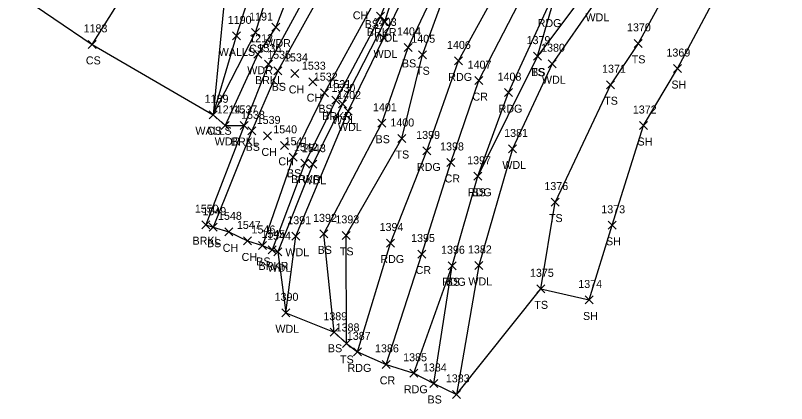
# Model space of a CAD drawing. Extents: x 1441651 to 1442140, y 243798 to 245625.
# Drawn here: x 1441936.1 to 1442128.7, y 245257.1 to 245354.1 of the extents above; entities that cross this region are included whole.
import ezdxf

# ---------------------------------------------------------------- set-up
doc = ezdxf.new("R2010")
doc.units = 0
for name, color, linetype in [('L_A', 7, 'Continuous'), ('L_I', 7, 'Continuous'), ('L_TIC', 7, 'Continuous'), ('LAWA', 7, 'Continuous'), ('LAWE', 7, 'Continuous'), ('LELB', 7, 'Continuous'), ('LSOGP', 7, 'Continuous'), ('LWS', 7, 'Continuous'), ('P_A', 7, 'Continuous'), ('P_I', 7, 'Continuous'), ('P_TIC', 7, 'Continuous'), ('PEU', 7, 'Continuous'), ('PRC', 7, 'Continuous')]:
    doc.layers.add(name, color=color, linetype=linetype)

msp = doc.modelspace()

# ---------------------------------------------------------------- linework, layer by layer
at = {"layer": 'L_TIC'}
for points in [[(1442026.29, 245352.92), (1442028.29, 245354.92)], [(1442028.29, 245352.92), (1442026.29, 245354.92)], [(1442000.16, 245350.18), (1442002.16, 245352.18)], [(1442002.16, 245350.18), (1442000.16, 245352.18)], [(1442027.33, 245351.53), (1442029.33, 245353.53)], [(1442029.33, 245351.53), (1442027.33, 245353.53)], [(1441990.35, 245347.99), (1441992.35, 245349.99)], [(1441992.35, 245347.99), (1441990.35, 245349.99)], [(1441995.05, 245348.81), (1441997.05, 245350.81)], [(1441997.05, 245348.81), (1441995.05, 245350.81)], [(1442027.14, 245347.48), (1442029.14, 245349.48)], [(1442029.14, 245347.48), (1442027.14, 245349.48)], [(1442090.63, 245346.12), (1442092.63, 245348.12)], [(1442092.63, 245346.12), (1442090.63, 245348.12)], [(1441954.27, 245345.86), (1441956.27, 245347.86)], [(1441956.27, 245345.86), (1441954.27, 245347.86)], [(1442033.2, 245345.11), (1442035.2, 245347.11)], [(1442035.2, 245345.11), (1442033.2, 245347.11)], [(1441995.64, 245343.41), (1441997.64, 245345.41)], [(1441997.64, 245343.41), (1441995.64, 245345.41)], [(1442036.76, 245343.27), (1442038.76, 245345.27)], [(1442038.76, 245343.27), (1442036.76, 245345.27)], [(1442065.47, 245342.93), (1442067.47, 245344.93)], [(1442067.47, 245342.93), (1442065.47, 245344.93)], [(1442065.47, 245342.93), (1442067.47, 245344.93)], [(1442067.47, 245342.93), (1442065.47, 245344.93)], [(1441998.31, 245340.93), (1442000.31, 245342.93)], [(1442000.31, 245340.93), (1441998.31, 245342.93)], [(1442069.18, 245341.03), (1442071.18, 245343.03)], [(1442071.18, 245341.03), (1442069.18, 245343.03)], [(1442000.68, 245339.27), (1442002.68, 245341.27)], [(1442002.68, 245339.27), (1442000.68, 245341.27)], [(1442004.9, 245338.6), (1442006.9, 245340.6)], [(1442006.9, 245338.6), (1442004.9, 245340.6)], [(1442100.45, 245339.82), (1442102.45, 245341.82)], [(1442102.45, 245339.82), (1442100.45, 245341.82)], [(1442009.36, 245336.54), (1442011.36, 245338.54)], [(1442011.36, 245336.54), (1442009.36, 245338.54)], [(1442083.74, 245335.78), (1442085.74, 245337.78)], [(1442085.74, 245335.78), (1442083.74, 245337.78)], [(1442012.33, 245333.79), (1442014.33, 245335.79)], [(1442014.33, 245333.79), (1442012.33, 245335.79)], [(1442015.14, 245331.93), (1442017.14, 245333.93)], [(1442017.14, 245331.93), (1442015.14, 245333.93)], [(1442016.83, 245330.97), (1442018.83, 245332.97)], [(1442018.83, 245330.97), (1442016.83, 245332.97)], [(1442018.24, 245329.2), (1442020.24, 245331.2)], [(1442020.24, 245329.2), (1442018.24, 245331.2)], [(1441984.51, 245328.27), (1441986.51, 245330.27)], [(1441986.51, 245328.27), (1441984.51, 245330.27)], [(1441984.51, 245328.27), (1441986.51, 245330.27)], [(1441986.51, 245328.27), (1441984.51, 245330.27)], [(1441987.52, 245325.61), (1441989.52, 245327.61)], [(1441989.52, 245325.61), (1441987.52, 245327.61)], [(1441992.28, 245325.59), (1441994.28, 245327.59)], [(1441994.28, 245325.59), (1441992.28, 245327.59)], [(1442026.62, 245326.16), (1442028.62, 245328.16)], [(1442028.62, 245326.16), (1442026.62, 245328.16)], [(1442092, 245325.58), (1442094, 245327.58)], [(1442094, 245325.58), (1442092, 245327.58)], [(1441994.17, 245324.26), (1441996.17, 245326.26)], [(1441996.17, 245324.26), (1441994.17, 245326.26)], [(1441998.07, 245322.98), (1442000.07, 245324.98)], [(1442000.07, 245322.98), (1441998.07, 245324.98)], [(1442031.62, 245322.34), (1442033.62, 245324.34)], [(1442033.62, 245322.34), (1442031.62, 245324.34)], [(1442002.29, 245320.63), (1442004.29, 245322.63)], [(1442004.29, 245320.63), (1442002.29, 245322.63)], [(1442059.29, 245319.73), (1442061.29, 245321.73)], [(1442061.29, 245319.73), (1442059.29, 245321.73)], [(1442004.48, 245317.66), (1442006.48, 245319.66)], [(1442006.48, 245317.66), (1442004.48, 245319.66)], [(1442007.36, 245316.18), (1442009.36, 245318.18)], [(1442009.36, 245316.18), (1442007.36, 245318.18)], [(1442009.38, 245315.92), (1442011.38, 245317.92)], [(1442011.38, 245315.92), (1442009.38, 245317.92)], [(1442050.62, 245312.9), (1442052.62, 245314.9)], [(1442052.62, 245312.9), (1442050.62, 245314.9)], [(1442069.95, 245306.45), (1442071.95, 245308.45)], [(1442071.95, 245306.45), (1442069.95, 245308.45)], [(1442069.95, 245306.45), (1442071.95, 245308.45)], [(1442071.95, 245306.45), (1442069.95, 245308.45)], [(1441982.7, 245300.8), (1441984.7, 245302.8)], [(1441984.7, 245300.8), (1441982.7, 245302.8)], [(1441984.52, 245300.17), (1441986.52, 245302.17)], [(1441986.52, 245300.17), (1441984.52, 245302.17)], [(1442084.12, 245300.65), (1442086.12, 245302.65)], [(1442086.12, 245300.65), (1442084.12, 245302.65)], [(1441988.4, 245299.01), (1441990.4, 245301.01)], [(1441990.4, 245299.01), (1441988.4, 245301.01)], [(1442005.13, 245297.92), (1442007.13, 245299.92)], [(1442007.13, 245297.92), (1442005.13, 245299.92)], [(1442012.15, 245298.51), (1442014.15, 245300.51)], [(1442014.15, 245298.51), (1442012.15, 245300.51)], [(1442017.73, 245298.13), (1442019.73, 245300.13)], [(1442019.73, 245298.13), (1442017.73, 245300.13)], [(1441993.11, 245296.74), (1441995.11, 245298.74)], [(1441995.11, 245296.74), (1441993.11, 245298.74)], [(1441996.83, 245295.61), (1441998.83, 245297.61)], [(1441998.83, 245295.61), (1441996.83, 245297.61)], [(1441999.26, 245294.5), (1442001.26, 245296.5)], [(1442001.26, 245294.5), (1441999.26, 245296.5)], [(1442000.66, 245294.02), (1442002.66, 245296.02)], [(1442002.66, 245294.02), (1442000.66, 245296.02)], [(1442044.15, 245290.53), (1442046.15, 245292.53)], [(1442046.15, 245290.53), (1442044.15, 245292.53)], [(1442050.82, 245290.62), (1442052.82, 245292.62)], [(1442052.82, 245290.62), (1442050.82, 245292.62)], [(1442066.31, 245284.77), (1442068.31, 245286.77)], [(1442068.31, 245284.77), (1442066.31, 245286.77)], [(1442078.37, 245281.99), (1442080.37, 245283.99)], [(1442080.37, 245281.99), (1442078.37, 245283.99)], [(1442002.62, 245278.78), (1442004.62, 245280.78)], [(1442004.62, 245278.78), (1442002.62, 245280.78)], [(1442014.72, 245273.92), (1442016.72, 245275.92)], [(1442016.72, 245273.92), (1442014.72, 245275.92)], [(1442017.78, 245271.12), (1442019.78, 245273.12)], [(1442019.78, 245271.12), (1442017.78, 245273.12)], [(1442039.59, 245261.12), (1442041.59, 245263.12)], [(1442041.59, 245261.12), (1442039.59, 245263.12)], [(1442045.29, 245258.4), (1442047.29, 245260.4)], [(1442047.29, 245258.4), (1442045.29, 245260.4)]]:
    msp.add_lwpolyline(points, dxfattribs=at)
at = {"layer": 'LAWA'}
for points in [[(1441938.82, 245423.16), (1441966.59, 245419.59), (1441980.43, 245407.31), (1441994.99, 245393.97), (1442005.69, 245385.38), (1442010.09, 245391.87), (1442016.01, 245382.46), (1442013.07, 245379.25), (1442007.39, 245367.36), (1442001.16, 245351.18), (1441996.64, 245344.41), (1441988.52, 245326.61)], [(1442003.62, 245279.78), (1442006.13, 245298.92), (1442019.24, 245330.2), (1442028.14, 245348.48), (1442037.74, 245368.51), (1442033.75, 245369.5), (1442028.33, 245352.53), (1442017.83, 245331.97), (1442010.38, 245316.92), (1442001.66, 245295.02)], [(1442081.06, 245357.62), (1442070.18, 245342.03), (1442060.29, 245320.73), (1442051.82, 245291.62), (1442046.29, 245259.4)]]:
    msp.add_lwpolyline(points, dxfattribs=at)
at = {"layer": 'LAWE'}
for points in [[(1442099.33, 245492.7), (1442082.17, 245474.83), (1442073.96, 245459.56), (1442071.04, 245454.67), (1442067.5, 245447.08), (1442064.77, 245439.02), (1442060.82, 245433.99), (1442057.71, 245424.57), (1442056.02, 245422.42), (1442050.95, 245416.77), (1442046.42, 245406.15), (1442038.47, 245397.39), (1442033, 245390.02), (1442022.03, 245379.96), (1442015.44, 245373.01), (1442011.82, 245364.95), (1441999.31, 245341.93), (1441993.28, 245326.59), (1441983.7, 245301.8)], [(1442108.8, 245476.47), (1442096.83, 245461.7), (1442085.94, 245448.64), (1442079.45, 245435.79), (1442078.13, 245432.44), (1442074.22, 245419.93), (1442069.91, 245412.33), (1442066.17, 245406.44), (1442060.08, 245400.81), (1442053.87, 245394.97), (1442048.8, 245389.02), (1442033.75, 245369.5), (1442027.29, 245353.92), (1442016.14, 245332.93), (1442008.36, 245317.18), (1442000.26, 245295.5)]]:
    msp.add_lwpolyline(points, dxfattribs=at)
at = {"layer": 'LELB'}
for points in [[(1442102.46, 245487.56), (1442084.35, 245473.24), (1442077.16, 245458.74), (1442072.72, 245452.8), (1442069.73, 245445.65), (1442066.87, 245437.14), (1442063.41, 245431.6), (1442060.35, 245422.41), (1442058.71, 245418.73), (1442054.41, 245414.05), (1442047.26, 245402.98), (1442041.76, 245394.88), (1442035.1, 245387.22), (1442025.14, 245377.83), (1442014.24, 245362.92), (1442001.68, 245340.27), (1441995.17, 245325.26), (1441985.52, 245301.17)], [(1442107.48, 245478.04), (1442095.11, 245463.14), (1442085.12, 245450.23), (1442079.93, 245439.38), (1442074.02, 245430.6), (1442072.19, 245422.42), (1442067.6, 245415.77), (1442063.53, 245410.87), (1442058.94, 245403.45), (1442051.47, 245396.66), (1442047.36, 245390.55), (1442031.62, 245371.64), (1442024.89, 245355.94), (1442013.33, 245334.79), (1442005.48, 245318.66), (1441997.83, 245296.61)], [(1442128.7, 245453.17), (1442114.47, 245439.46), (1442106.29, 245436.04), (1442091.13, 245416.25), (1442087.36, 245410.97), (1442078.92, 245407.7), (1442072.37, 245401.79), (1442078.66, 245393.32), (1442088.17, 245379.01), (1442078.35, 245359.72), (1442066.47, 245343.93), (1442051.62, 245313.9)], [(1442126.3, 245425.7), (1442121.34, 245419.96), (1442113.11, 245400.1), (1442105.87, 245373.18), (1442091.63, 245347.12), (1442084.74, 245336.78), (1442070.95, 245307.45)], [(1442066.47, 245343.93), (1442078.11, 245383.77), (1442072.28, 245394.26)], [(1441955.27, 245346.86), (1441965.21, 245362.63), (1441976.13, 245373.64), (1441994.99, 245393.97), (1441992.5, 245375.66), (1441988.38, 245359.29), (1441985.51, 245329.27), (1441996.05, 245349.81), (1442001.58, 245367.37), (1442003.86, 245377.37), (1442005.69, 245385.38), (1442010.09, 245391.87)], [(1442018.78, 245272.12), (1442018.73, 245299.13), (1442032.62, 245323.34), (1442037.76, 245344.27), (1442043.41, 245359.74), (1442052.17, 245365.32), (1442056.49, 245374.23), (1442057.59, 245382.34)], [(1442015.72, 245274.92), (1442013.15, 245299.51), (1442027.62, 245327.16), (1442034.2, 245346.11), (1442043.81, 245366.33)], [(1442067.31, 245285.77), (1442070.95, 245307.45)], [(1442040.59, 245262.12), (1442045.15, 245291.53)]]:
    msp.add_lwpolyline(points, dxfattribs=at)
at = {"layer": 'LSOGP'}
msp.add_lwpolyline([(1441936.12, 245359.87), (1441955.27, 245346.86), (1441985.51, 245329.27), (1441988.52, 245326.61), (1441993.28, 245326.59), (1441983.7, 245301.8), (1441985.52, 245301.17), (1441989.4, 245300.01), (1441994.11, 245297.74), (1441997.83, 245296.61), (1442000.26, 245295.5), (1442001.66, 245295.02), (1442003.62, 245279.78), (1442015.72, 245274.92), (1442018.78, 245272.12), (1442021.57, 245270.01), (1442028.67, 245266.9), (1442035.64, 245264.67), (1442040.59, 245262.12), (1442046.29, 245259.4), (1442067.31, 245285.77), (1442079.37, 245282.99), (1442085.12, 245301.65), (1442093, 245326.58), (1442101.45, 245340.82), (1442116.12, 245368.4)], dxfattribs=at)
at = {"layer": 'LWS'}
msp.add_lwpolyline([(1441985.51, 245329.27), (1441991.35, 245348.99), (1441998.11, 245370.16), (1442003.86, 245377.37), (1442013.07, 245379.25)], dxfattribs=at)
at = {"layer": 'P_TIC'}
for points in [[(1442045.73, 245341.73), (1442047.73, 245343.73)], [(1442047.73, 245341.73), (1442045.73, 245343.73)], [(1442050.82, 245336.8), (1442052.82, 245338.8)], [(1442052.82, 245336.8), (1442050.82, 245338.8)], [(1442058.29, 245333.8), (1442060.29, 245335.8)], [(1442060.29, 245333.8), (1442058.29, 245335.8)], [(1442037.9, 245319.23), (1442039.9, 245321.23)], [(1442039.9, 245319.23), (1442037.9, 245321.23)], [(1442043.86, 245316.35), (1442045.86, 245318.35)], [(1442045.86, 245316.35), (1442043.86, 245318.35)], [(1442050.62, 245312.9), (1442052.62, 245314.9)], [(1442052.62, 245312.9), (1442050.62, 245314.9)], [(1442028.76, 245296.22), (1442030.76, 245298.22)], [(1442030.76, 245296.22), (1442028.76, 245298.22)], [(1442036.62, 245293.47), (1442038.62, 245295.47)], [(1442038.62, 245293.47), (1442036.62, 245295.47)], [(1442044.15, 245290.53), (1442046.15, 245292.53)], [(1442046.15, 245290.53), (1442044.15, 245292.53)], [(1442020.57, 245269.01), (1442022.57, 245271.01)], [(1442022.57, 245269.01), (1442020.57, 245271.01)], [(1442027.67, 245265.9), (1442029.67, 245267.9)], [(1442029.67, 245265.9), (1442027.67, 245267.9)], [(1442034.64, 245263.67), (1442036.64, 245265.67)], [(1442036.64, 245263.67), (1442034.64, 245265.67)]]:
    msp.add_lwpolyline(points, dxfattribs=at)
at = {"layer": 'PEU'}
for points in [[(1442021.57, 245270.01), (1442029.76, 245297.22), (1442038.9, 245320.23), (1442046.73, 245342.73), (1442056.78, 245360.96), (1442059.33, 245377.92), (1442059.51, 245384.26), (1442055.55, 245392.58), (1442060.31, 245397.75), (1442066.08, 245403.51)], [(1442035.64, 245264.67), (1442045.15, 245291.53), (1442051.62, 245313.9), (1442059.29, 245334.8), (1442069.06, 245356.18), (1442072.88, 245382.67), (1442066.08, 245403.51)]]:
    msp.add_lwpolyline(points, dxfattribs=at)
at = {"layer": 'PRC'}
msp.add_lwpolyline([(1442028.67, 245266.9), (1442037.62, 245294.47), (1442044.86, 245317.35), (1442051.82, 245337.8), (1442063.02, 245359.5), (1442065.73, 245381.39), (1442063.41, 245391.64), (1442060.31, 245397.75)], dxfattribs=at)

# ---------------------------------------------------------------- texts
at = {"layer": 'L_A'}
for s, p in [('CH', (1442020.38, 245353.12)), ('WDL', (1442078.48, 245352.62)), ('BS', (1442023.33, 245350.94)), ('BRKR', (1442023.89, 245348.92)), ('WDR', (1441998.52, 245346.18)), ('WDL', (1442025.75, 245347.53)), ('WALLS', (1441986.89, 245343.99)), ('CS', (1441994.49, 245344.81)), ('WDL', (1442025.56, 245343.48)), ('TS', (1442090.03, 245342.12)), ('CS', (1441953.71, 245341.86)), ('BS', (1442032.64, 245341.11)), ('WDR', (1441994, 245339.41)), ('TS', (1442036.17, 245339.27)), ('TS', (1442064.88, 245338.93)), ('BS', (1442064.91, 245338.93)), ('BRKL', (1441995.96, 245336.93)), ('WDL', (1442067.6, 245337.03)), ('BS', (1442000.12, 245335.27)), ('CH', (1442004.39, 245334.6)), ('SH', (1442099.94, 245335.82)), ('CH', (1442008.85, 245332.54)), ('TS', (1442083.15, 245331.78)), ('BS', (1442011.77, 245329.79)), ('BRKR', (1442012.73, 245327.93)), ('WDL', (1442015.25, 245326.97)), ('WDL', (1442016.66, 245325.2)), ('WALLS', (1441981.06, 245324.27)), ('CS', (1441983.96, 245324.27)), ('WDR', (1441985.88, 245321.61)), ('BRKL', (1441989.92, 245321.59)), ('BS', (1442026.06, 245322.16)), ('SH', (1442091.48, 245321.58)), ('BS', (1441993.61, 245320.26)), ('CH', (1441997.56, 245318.98)), ('TS', (1442031.03, 245318.34)), ('CH', (1442001.78, 245316.63)), ('WDL', (1442057.71, 245315.73)), ('BS', (1442003.92, 245313.66)), ('BRKR', (1442004.95, 245312.18)), ('WDL', (1442007.79, 245311.92)), ('BS', (1442050.06, 245308.9)), ('TS', (1442069.36, 245302.45)), ('TS', (1442069.36, 245302.45)), ('BRKL', (1441980.34, 245296.8)), ('BS', (1441983.96, 245296.17)), ('SH', (1442083.61, 245296.65)), ('CH', (1441987.89, 245295.01)), ('BS', (1442011.59, 245294.51)), ('TS', (1442017.14, 245294.13)), ('CH', (1441992.6, 245292.74)), ('WDL', (1442003.55, 245293.92)), ('BS', (1441996.27, 245291.61)), ('BRKR', (1441996.85, 245290.5)), ('WDL', (1441999.08, 245290.02)), ('BS', (1442043.6, 245286.53)), ('WDL', (1442049.24, 245286.62)), ('TS', (1442065.72, 245280.77)), ('SH', (1442077.86, 245277.99)), ('WDL', (1442001.04, 245274.78)), ('BS', (1442014.16, 245269.92)), ('TS', (1442017.19, 245267.12)), ('BS', (1442039.03, 245257.12))]:
    msp.add_text(s, height=2, dxfattribs=at).set_placement(p)
at = {"layer": 'L_I'}
for s, p in [('1190', (1441989.14, 245351.99)), ('1191', (1441994.49, 245352.81)), ('1183', (1441953.14, 245349.86)), ('1403', (1442025.37, 245351.48)), ('1370', (1442088.85, 245350.12)), ('1404', (1442031.42, 245349.11)), ('1213', (1441994.51, 245347.41)), ('1405', (1442034.99, 245347.27)), ('1379', (1442063.77, 245346.93)), ('1379', (1442063.77, 245346.93)), ('1536', (1441996.56, 245344.93)), ('1380', (1442067.4, 245345.03)), ('1535', (1441998.99, 245343.27)), ('1534', (1442003.2, 245342.6)), ('1369', (1442098.7, 245343.82)), ('1533', (1442007.66, 245340.54)), ('1371', (1442082.62, 245339.78)), ('1532', (1442010.64, 245337.79)), ('1531', (1442014.02, 245335.93)), ('1530', (1442015.05, 245334.97)), ('1402', (1442016.47, 245333.2)), ('1189', (1441983.38, 245332.27)), ('1189', (1441983.38, 245332.27)), ('1214', (1441986.39, 245329.61)), ('1537', (1441990.58, 245329.59)), ('1401', (1442025.41, 245330.16)), ('1372', (1442090.3, 245329.58)), ('1538', (1441992.47, 245328.26)), ('1539', (1441996.37, 245326.98)), ('1400', (1442029.76, 245326.34)), ('1540', (1442000.51, 245324.63)), ('1381', (1442058.17, 245323.73)), ('1541', (1442003.35, 245321.66)), ('1542', (1442005.67, 245320.18)), ('1543', (1442007.68, 245319.92)), ('1397', (1442048.93, 245316.9)), ('1376', (1442068.21, 245310.45)), ('1376', (1442068.21, 245310.45)), ('1550', (1441980.92, 245304.8)), ('1549', (1441982.82, 245304.17)), ('1373', (1442082.43, 245304.65)), ('1548', (1441986.71, 245303.01)), ('1391', (1442004.01, 245301.92)), ('1392', (1442010.45, 245302.51)), ('1393', (1442016.03, 245302.13)), ('1547', (1441991.42, 245300.74)), ('1546', (1441995.08, 245299.61)), ('1545', (1441997.57, 245298.5)), ('1544', (1441998.97, 245298.02)), ('1396', (1442042.41, 245294.53)), ('1382', (1442049.13, 245294.62)), ('1375', (1442064.61, 245288.77)), ('1374', (1442076.68, 245285.99)), ('1390', (1442000.84, 245282.78)), ('1389', (1442013.02, 245277.92)), ('1388', (1442016.09, 245275.12)), ('1384', (1442037.89, 245265.12)), ('1383', (1442043.6, 245262.4))]:
    msp.add_text(s, height=2, dxfattribs=at).set_placement(p)
at = {"layer": 'P_A'}
for s, p in [('RDG', (1442066.54, 245351.18)), ('RDG', (1442044.21, 245337.73)), ('CR', (1442050.25, 245332.8)), ('RDG', (1442056.78, 245329.8)), ('RDG', (1442036.39, 245315.23)), ('CR', (1442043.29, 245312.35)), ('RDG', (1442049.11, 245308.9)), ('RDG', (1442027.25, 245292.22)), ('CR', (1442036.06, 245289.47)), ('RDG', (1442042.64, 245286.53)), ('RDG', (1442019.06, 245265.01)), ('CR', (1442027.1, 245261.9)), ('RDG', (1442033.13, 245259.67))]:
    msp.add_text(s, height=2, dxfattribs=at).set_placement(p)
at = {"layer": 'P_I'}
for s, p in [('1406', (1442043.9, 245345.73)), ('1407', (1442049.05, 245340.8)), ('1408', (1442056.52, 245337.8)), ('1399', (1442036.2, 245323.23)), ('1398', (1442042.17, 245320.35)), ('1397', (1442048.93, 245316.9)), ('1394', (1442027.07, 245300.22)), ('1395', (1442034.93, 245297.47)), ('1396', (1442042.41, 245294.53)), ('1387', (1442018.88, 245273.01)), ('1386', (1442025.92, 245269.9)), ('1385', (1442032.95, 245267.67))]:
    msp.add_text(s, height=2, dxfattribs=at).set_placement(p)

doc.saveas('drawing.dxf')
